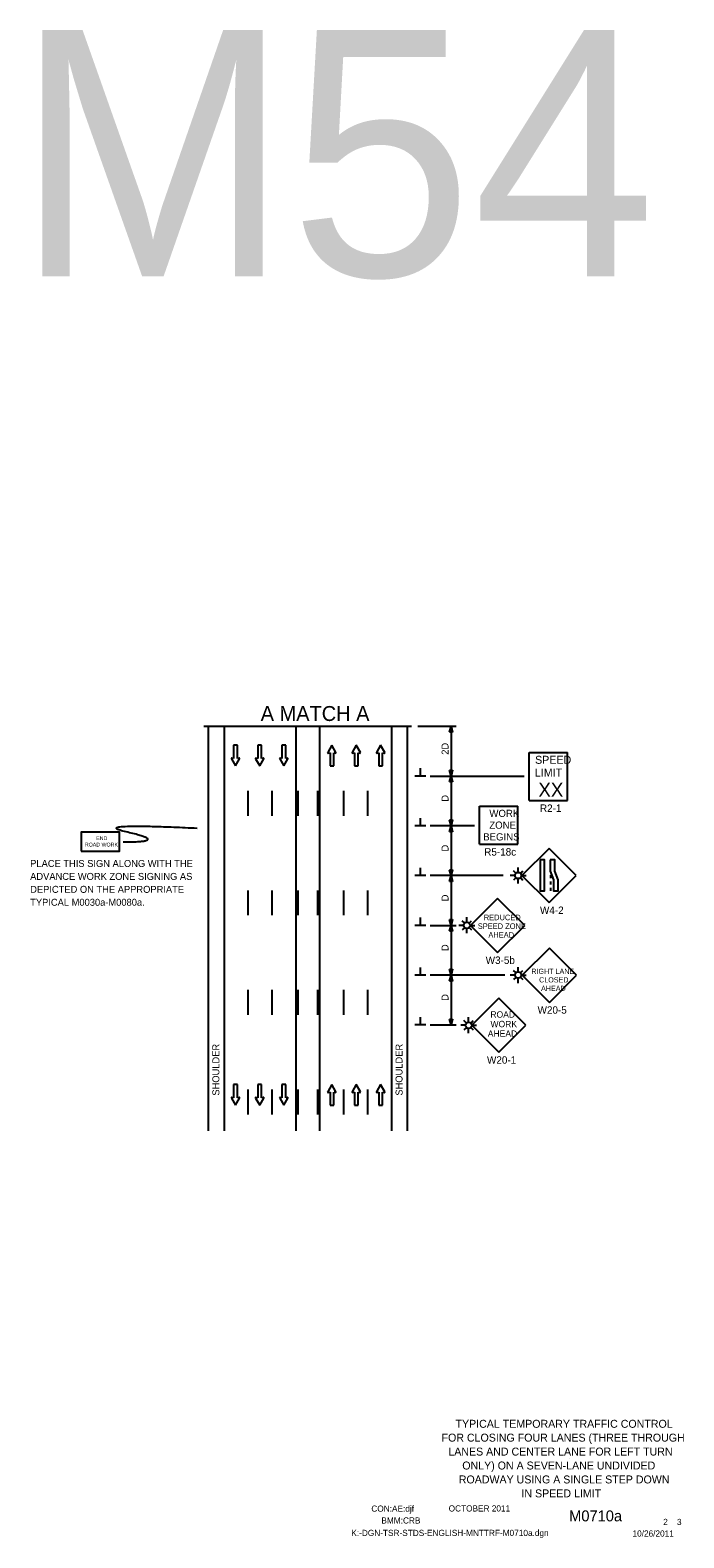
# Model space of a CAD drawing. Extents: x 16731 to 19504, y 5932 to 7446.
# Drawn here: x 17777 to 18433, y 5932 to 7446 of the extents above; entities that cross this region are included whole.
import ezdxf

# ---------------------------------------------------------------- set-up
doc = ezdxf.new("R2010")
doc.units = 0
for name, color, linetype in [('ALI_LEGAL_EX', 7, 'Continuous'), ('BORDER', 7, 'Continuous'), ('BORDER_SIGNAL_WO', 7, 'Continuous'), ('MT_SCRATCH_LEVEL_E', 7, 'Continuous'), ('PAVT_EDGE_EX', 7, 'Continuous'), ('TRAFFIC_SIGNS_PR', 7, 'Continuous'), ('TYPICAL_TEXT_DIMEN_PR', 7, 'Continuous')]:
    doc.layers.add(name, color=color, linetype=linetype)

msp = doc.modelspace()

# ---------------------------------------------------------------- linework, layer by layer
at = {"layer": 'ALI_LEGAL_EX'}
for points in [[(17995.8, 6682.2), (17995.8, 6657.2)], [(18019.8, 6682.2), (18019.8, 6657.2)], [(18045.8, 6682.2), (18045.8, 6657.2)], [(18065.8, 6682.2), (18065.8, 6657.2)], [(18091.8, 6682.2), (18091.8, 6657.2)], [(18115.8, 6682.2), (18115.8, 6657.2)], [(17995.8, 6582.2), (17995.8, 6557.2)], [(18019.8, 6582.2), (18019.8, 6557.2)], [(18045.8, 6582.2), (18045.8, 6557.2)], [(18065.8, 6582.2), (18065.8, 6557.2)], [(18091.8, 6582.2), (18091.8, 6557.2)], [(18115.8, 6582.2), (18115.8, 6557.2)], [(17995.8, 6482.2), (17995.8, 6457.2)], [(18019.8, 6482.2), (18019.8, 6457.2)], [(18045.8, 6482.2), (18045.8, 6457.2)], [(18065.8, 6482.2), (18065.8, 6457.2)], [(18091.8, 6482.2), (18091.8, 6457.2)], [(18115.8, 6482.2), (18115.8, 6457.2)], [(17995.8, 6382.2), (17995.8, 6357.2)], [(18019.8, 6382.2), (18019.8, 6357.2)], [(18045.8, 6382.2), (18045.8, 6357.2)], [(18065.8, 6382.2), (18065.8, 6357.2)], [(18091.8, 6382.2), (18091.8, 6357.2)], [(18115.8, 6382.2), (18115.8, 6357.2)]]:
    msp.add_lwpolyline(points, dxfattribs=at)
at = {"layer": 'BORDER'}
msp.add_line((18318.2, 6011.2), (18318.2, 6011.2), dxfattribs=at)
msp.add_line((18318.2, 6011.2), (18318.2, 6011.2), dxfattribs=at)
at = {"layer": 'MT_SCRATCH_LEVEL_E'}
for p, q in [((17985.2, 6727.9), (17981.4, 6727.9)), ((17981.4, 6727.9), (17981.4, 6714.7)), ((17985.2, 6727.9), (17981.4, 6727.9)), ((17981.4, 6727.9), (17981.4, 6714.7)), ((17985.2, 6714.7), (17985.2, 6727.9)), ((17985.2, 6714.7), (17985.2, 6727.9)), ((18009.4, 6727.9), (18005.7, 6727.9)), ((18005.7, 6727.9), (18005.7, 6714.7)), ((18009.4, 6727.9), (18005.7, 6727.9)), ((18005.7, 6727.9), (18005.7, 6714.7)), ((18009.4, 6714.7), (18009.4, 6727.9)), ((18009.4, 6714.7), (18009.4, 6727.9)), ((18033.7, 6727.9), (18030, 6727.9)), ((18030, 6727.9), (18030, 6714.7)), ((18033.7, 6727.9), (18030, 6727.9)), ((18030, 6727.9), (18030, 6714.7)), ((18033.7, 6714.7), (18033.7, 6727.9)), ((18033.7, 6714.7), (18033.7, 6727.9)), ((18080, 6727.9), (18075.9, 6720.7)), ((18080, 6727.9), (18075.9, 6720.7)), ((18084.2, 6720.7), (18080, 6727.9)), ((18084.2, 6720.7), (18080, 6727.9)), ((18104.5, 6727.9), (18100.4, 6720.7)), ((18104.5, 6727.9), (18100.4, 6720.7)), ((18108.7, 6720.7), (18104.5, 6727.9)), ((18108.7, 6720.7), (18104.5, 6727.9)), ((18129, 6727.9), (18124.9, 6720.7)), ((18129, 6727.9), (18124.9, 6720.7)), ((18133.2, 6720.7), (18129, 6727.9)), ((18133.2, 6720.7), (18129, 6727.9)), ((17979.2, 6714.3), (17983.3, 6707.1)), ((17979.2, 6714.3), (17983.3, 6707.1)), ((17981.4, 6714.7), (17979.7, 6715)), ((17981.4, 6714.7), (17979.7, 6715)), ((17983.3, 6707.1), (17987.4, 6714.3)), ((17983.3, 6707.1), (17987.4, 6714.3)), ((17987, 6715), (17985.2, 6714.7)), ((17987, 6715), (17985.2, 6714.7)), ((18003.4, 6714.3), (18007.6, 6707.1)), ((18003.4, 6714.3), (18007.6, 6707.1)), ((18005.7, 6714.7), (18003.9, 6715)), ((18005.7, 6714.7), (18003.9, 6715)), ((18007.6, 6707.1), (18011.7, 6714.3)), ((18007.6, 6707.1), (18011.7, 6714.3)), ((18011.2, 6715), (18009.4, 6714.7)), ((18011.2, 6715), (18009.4, 6714.7)), ((18027.7, 6714.3), (18031.8, 6707.1)), ((18027.7, 6714.3), (18031.8, 6707.1)), ((18030, 6714.7), (18028.2, 6715)), ((18030, 6714.7), (18028.2, 6715)), ((18031.8, 6707.1), (18036, 6714.3)), ((18031.8, 6707.1), (18036, 6714.3)), ((18035.5, 6715), (18033.7, 6714.7)), ((18035.5, 6715), (18033.7, 6714.7)), ((18076.4, 6720), (18078.2, 6720.3)), ((18076.4, 6720), (18078.2, 6720.3)), ((18078.2, 6720.3), (18078.2, 6707.1)), ((18078.2, 6720.3), (18078.2, 6707.1)), ((18081.9, 6707.1), (18081.9, 6720.3)), ((18081.9, 6720.3), (18083.7, 6720)), ((18081.9, 6707.1), (18081.9, 6720.3)), ((18081.9, 6720.3), (18083.7, 6720)), ((18100.9, 6720), (18102.7, 6720.3)), ((18100.9, 6720), (18102.7, 6720.3)), ((18102.7, 6720.3), (18102.7, 6707.1)), ((18102.7, 6720.3), (18102.7, 6707.1)), ((18106.4, 6707.1), (18106.4, 6720.3)), ((18106.4, 6720.3), (18108.2, 6720)), ((18106.4, 6707.1), (18106.4, 6720.3)), ((18106.4, 6720.3), (18108.2, 6720)), ((18125.4, 6720), (18127.2, 6720.3)), ((18125.4, 6720), (18127.2, 6720.3)), ((18127.2, 6720.3), (18127.2, 6707.1)), ((18127.2, 6720.3), (18127.2, 6707.1)), ((18130.9, 6707.1), (18130.9, 6720.3)), ((18130.9, 6720.3), (18132.7, 6720)), ((18130.9, 6707.1), (18130.9, 6720.3)), ((18130.9, 6720.3), (18132.7, 6720)), ((18078.2, 6707.1), (18081.9, 6707.1)), ((18078.2, 6707.1), (18081.9, 6707.1)), ((18102.7, 6707.1), (18106.4, 6707.1)), ((18102.7, 6707.1), (18106.4, 6707.1)), ((18127.2, 6707.1), (18130.9, 6707.1)), ((18127.2, 6707.1), (18130.9, 6707.1)), ((17985.2, 6387.1), (17981.4, 6387.1)), ((17981.4, 6387.1), (17981.4, 6373.9)), ((17985.2, 6387.1), (17981.4, 6387.1)), ((17981.4, 6387.1), (17981.4, 6373.9)), ((17985.2, 6373.9), (17985.2, 6387.1)), ((17985.2, 6373.9), (17985.2, 6387.1)), ((18009.4, 6387.1), (18005.7, 6387.1)), ((18005.7, 6387.1), (18005.7, 6373.9)), ((18009.4, 6387.1), (18005.7, 6387.1)), ((18005.7, 6387.1), (18005.7, 6373.9)), ((18009.4, 6373.9), (18009.4, 6387.1)), ((18009.4, 6373.9), (18009.4, 6387.1)), ((18033.7, 6387.1), (18030, 6387.1)), ((18030, 6387.1), (18030, 6373.9)), ((18033.7, 6387.1), (18030, 6387.1)), ((18030, 6387.1), (18030, 6373.9)), ((18033.7, 6373.9), (18033.7, 6387.1)), ((18033.7, 6373.9), (18033.7, 6387.1)), ((18080, 6387.1), (18075.9, 6379.9)), ((18080, 6387.1), (18075.9, 6379.9)), ((18076.4, 6379.2), (18078.2, 6379.5)), ((18076.4, 6379.2), (18078.2, 6379.5)), ((18078.2, 6379.5), (18078.2, 6366.3)), ((18078.2, 6379.5), (18078.2, 6366.3)), ((18084.2, 6379.9), (18080, 6387.1)), ((18084.2, 6379.9), (18080, 6387.1)), ((18081.9, 6366.3), (18081.9, 6379.5)), ((18081.9, 6379.5), (18083.7, 6379.2)), ((18081.9, 6366.3), (18081.9, 6379.5)), ((18081.9, 6379.5), (18083.7, 6379.2)), ((18104.5, 6387.1), (18100.4, 6379.9)), ((18104.5, 6387.1), (18100.4, 6379.9)), ((18100.9, 6379.2), (18102.7, 6379.5)), ((18100.9, 6379.2), (18102.7, 6379.5)), ((18102.7, 6379.5), (18102.7, 6366.3)), ((18102.7, 6379.5), (18102.7, 6366.3)), ((18108.7, 6379.9), (18104.5, 6387.1)), ((18108.7, 6379.9), (18104.5, 6387.1)), ((18106.4, 6366.3), (18106.4, 6379.5)), ((18106.4, 6379.5), (18108.2, 6379.2)), ((18106.4, 6366.3), (18106.4, 6379.5)), ((18106.4, 6379.5), (18108.2, 6379.2)), ((18129, 6387.1), (18124.9, 6379.9)), ((18129, 6387.1), (18124.9, 6379.9)), ((18125.4, 6379.2), (18127.2, 6379.5)), ((18125.4, 6379.2), (18127.2, 6379.5)), ((18127.2, 6379.5), (18127.2, 6366.3)), ((18127.2, 6379.5), (18127.2, 6366.3)), ((18133.2, 6379.9), (18129, 6387.1)), ((18133.2, 6379.9), (18129, 6387.1)), ((18130.9, 6366.3), (18130.9, 6379.5)), ((18130.9, 6379.5), (18132.7, 6379.2)), ((18130.9, 6366.3), (18130.9, 6379.5)), ((18130.9, 6379.5), (18132.7, 6379.2)), ((17979.2, 6373.5), (17983.3, 6366.3)), ((17979.2, 6373.5), (17983.3, 6366.3)), ((17981.4, 6373.9), (17979.7, 6374.2)), ((17981.4, 6373.9), (17979.7, 6374.2)), ((17983.3, 6366.3), (17987.4, 6373.5)), ((17983.3, 6366.3), (17987.4, 6373.5)), ((17987, 6374.2), (17985.2, 6373.9)), ((17987, 6374.2), (17985.2, 6373.9)), ((18003.4, 6373.5), (18007.6, 6366.3)), ((18003.4, 6373.5), (18007.6, 6366.3)), ((18005.7, 6373.9), (18003.9, 6374.2)), ((18005.7, 6373.9), (18003.9, 6374.2)), ((18007.6, 6366.3), (18011.7, 6373.5)), ((18007.6, 6366.3), (18011.7, 6373.5)), ((18011.2, 6374.2), (18009.4, 6373.9)), ((18011.2, 6374.2), (18009.4, 6373.9)), ((18027.7, 6373.5), (18031.8, 6366.3)), ((18027.7, 6373.5), (18031.8, 6366.3)), ((18030, 6373.9), (18028.2, 6374.2)), ((18030, 6373.9), (18028.2, 6374.2)), ((18031.8, 6366.3), (18036, 6373.5)), ((18031.8, 6366.3), (18036, 6373.5)), ((18035.5, 6374.2), (18033.7, 6373.9)), ((18035.5, 6374.2), (18033.7, 6373.9)), ((18078.2, 6366.3), (18081.9, 6366.3)), ((18078.2, 6366.3), (18081.9, 6366.3)), ((18102.7, 6366.3), (18106.4, 6366.3)), ((18102.7, 6366.3), (18106.4, 6366.3)), ((18127.2, 6366.3), (18130.9, 6366.3)), ((18127.2, 6366.3), (18130.9, 6366.3))]:
    msp.add_line(p, q, dxfattribs=at)
for centre, start, end in [((17979.6, 6714.5), 80.0362, 209.7731), ((17979.6, 6714.5), 80.0362, 209.7731), ((17987, 6714.5), 330.4248, 99.9638), ((17987, 6714.5), 330.4248, 99.9638), ((18003.8, 6714.5), 80.0362, 209.7731), ((18003.8, 6714.5), 80.0362, 209.7731), ((18011.3, 6714.5), 330.4248, 99.9638), ((18011.3, 6714.5), 330.4248, 99.9638), ((18028.1, 6714.5), 80.0362, 209.7731), ((18028.1, 6714.5), 80.0362, 209.7731), ((18035.5, 6714.5), 330.4248, 99.9638), ((18035.5, 6714.5), 330.4248, 99.9638), ((18076.3, 6720.5), 150.4248, 279.9638), ((18076.3, 6720.5), 150.4248, 279.9638), ((18083.7, 6720.5), 260.0362, 29.7731), ((18083.7, 6720.5), 260.0362, 29.7731), ((18100.8, 6720.5), 150.4248, 279.9638), ((18100.8, 6720.5), 150.4248, 279.9638), ((18108.2, 6720.5), 260.0362, 29.7731), ((18108.2, 6720.5), 260.0362, 29.7731), ((18125.3, 6720.5), 150.4248, 279.9638), ((18125.3, 6720.5), 150.4248, 279.9638), ((18132.7, 6720.5), 260.0362, 29.7731), ((18132.7, 6720.5), 260.0362, 29.7731), ((18076.3, 6379.7), 150.4248, 279.9638), ((18076.3, 6379.7), 150.4248, 279.9638), ((18083.7, 6379.7), 260.0362, 29.7731), ((18083.7, 6379.7), 260.0362, 29.7731), ((18100.8, 6379.7), 150.4248, 279.9638), ((18100.8, 6379.7), 150.4248, 279.9638), ((18108.2, 6379.7), 260.0362, 29.7731), ((18108.2, 6379.7), 260.0362, 29.7731), ((18125.3, 6379.7), 150.4248, 279.9638), ((18125.3, 6379.7), 150.4248, 279.9638), ((18132.7, 6379.7), 260.0362, 29.7731), ((18132.7, 6379.7), 260.0362, 29.7731), ((17979.6, 6373.7), 80.0362, 209.7731), ((17979.6, 6373.7), 80.0362, 209.7731), ((17987, 6373.7), 330.4248, 99.9638), ((17987, 6373.7), 330.4248, 99.9638), ((18003.8, 6373.7), 80.0362, 209.7731), ((18003.8, 6373.7), 80.0362, 209.7731), ((18011.3, 6373.7), 330.4248, 99.9638), ((18011.3, 6373.7), 330.4248, 99.9638), ((18028.1, 6373.7), 80.0362, 209.7731), ((18028.1, 6373.7), 80.0362, 209.7731), ((18035.5, 6373.7), 330.4248, 99.9638), ((18035.5, 6373.7), 330.4248, 99.9638)]:
    msp.add_arc(centre, 0.463, start, end, dxfattribs=at)
at = {"layer": 'PAVT_EDGE_EX'}
for p, q in [((17955.8, 6747), (17955.8, 6340.8)), ((17971.8, 6747), (17971.8, 6340.8)), ((18043.8, 6747), (18043.8, 6340.8)), ((18067.8, 6747), (18067.8, 6340.8)), ((18139.8, 6747), (18139.8, 6340.8)), ((18155.8, 6747), (18155.8, 6340.8))]:
    msp.add_line(p, q, dxfattribs=at)
at = {"layer": 'TRAFFIC_SIGNS_PR'}
for p, q in [((18278.3, 6720.5), (18316.7, 6720.5)), ((18278.3, 6672.5), (18278.3, 6720.5)), ((18316.7, 6672.5), (18316.7, 6720.5)), ((18228.2, 6628.5), (18228.2, 6666.9)), ((18228.2, 6666.9), (18266.6, 6666.9)), ((18266.6, 6628.5), (18266.6, 6666.9)), ((18278.3, 6672.5), (18316.7, 6672.5)), ((18228.2, 6628.5), (18266.6, 6628.5)), ((18298.1, 6624.2), (18270.9, 6597.1)), ((18325.2, 6597.1), (18298.1, 6624.2)), ((18267.1, 6600.6), (18267.1, 6605.1)), ((18264, 6597.1), (18259.1, 6597.1)), ((18264.6, 6599.6), (18262.5, 6601.7)), ((18264.6, 6594.6), (18262.5, 6592.4)), ((18267.1, 6589.1), (18267.1, 6593.5)), ((18269.7, 6599.6), (18271.8, 6601.7)), ((18269.7, 6594.6), (18271.8, 6592.4)), ((18270.3, 6597.1), (18275.2, 6597.1)), ((18270.9, 6597.1), (18298.1, 6569.9)), ((18298.1, 6569.9), (18325.2, 6597.1)), ((18299.7, 6597.6), (18299.7, 6594.4)), ((18299.7, 6591.2), (18299.7, 6588)), ((18246.5, 6574.1), (18219.4, 6546.9)), ((18273.7, 6546.9), (18246.5, 6574.1)), ((18299.7, 6584.8), (18299.7, 6581.6)), ((18212.5, 6547), (18207.6, 6547)), ((18213.1, 6549.6), (18211, 6551.7)), ((18213.1, 6544.5), (18211, 6542.4)), ((18215.6, 6550.6), (18215.6, 6555.1)), ((18215.6, 6539.1), (18215.6, 6543.5)), ((18218.1, 6549.6), (18220.2, 6551.7)), ((18218.1, 6544.5), (18220.2, 6542.4)), ((18218.8, 6547), (18223.7, 6547)), ((18219.4, 6546.9), (18246.5, 6519.8)), ((18246.5, 6519.8), (18273.7, 6546.9)), ((18298.4, 6524), (18271.2, 6496.9)), ((18325.5, 6496.9), (18298.4, 6524)), ((18264, 6497.1), (18259.1, 6497.1)), ((18264.6, 6499.6), (18262.5, 6501.7)), ((18267.1, 6500.6), (18267.1, 6505.1)), ((18269.7, 6499.6), (18271.8, 6501.7)), ((18270.3, 6497.1), (18275.2, 6497.1)), ((18271.2, 6496.9), (18298.4, 6469.7)), ((18298.4, 6469.7), (18325.5, 6496.9)), ((18264.6, 6494.6), (18262.5, 6492.5)), ((18267.1, 6489.1), (18267.1, 6493.5)), ((18269.7, 6494.6), (18271.8, 6492.5)), ((18247.7, 6473.9), (18220.5, 6446.7)), ((18274.9, 6446.7), (18247.7, 6473.9)), ((18214.8, 6449.2), (18212.7, 6451.4)), ((18217.3, 6450.3), (18217.3, 6454.8)), ((18219.9, 6449.2), (18222, 6451.4)), ((18214.2, 6446.7), (18209.4, 6446.7)), ((18214.8, 6444.2), (18212.7, 6442.1)), ((18217.3, 6438.8), (18217.3, 6443.2)), ((18219.9, 6444.2), (18222, 6442.1)), ((18220.5, 6446.7), (18225.4, 6446.7)), ((18220.5, 6446.7), (18247.7, 6419.5)), ((18247.7, 6419.5), (18274.9, 6446.7))]:
    msp.add_line(p, q, dxfattribs=at)
for points in [[(17828.5, 6621.4), (17866.9, 6621.4), (17866.9, 6640.6), (17828.5, 6640.6)], [(18289.2, 6612.8), (18289.2, 6581.6), (18293.6, 6581.6), (18293.6, 6612.8)], [(18299.3, 6612.8), (18299.3, 6601.6), (18302.6, 6592.7), (18302.6, 6581.6), (18307.1, 6581.6), (18307.1, 6592.7), (18303.8, 6601.6), (18303.8, 6612.8)]]:
    msp.add_lwpolyline(points, close=True, dxfattribs=at)
for centre in [(18267.1, 6597.1), (18215.6, 6547), (18267.1, 6497.1), (18217.4, 6446.7)]:
    msp.add_circle(centre, 3.15, dxfattribs=at)
msp.add_open_spline([(17870.4, 6630.8), (17917.7, 6630.8), (17832.7, 6650.2), (17945, 6644.7)], degree=2, dxfattribs=at)
at = {"layer": 'TYPICAL_TEXT_DIMEN_PR'}
for p, q in [((17951.5, 6747), (18160.1, 6747)), ((18043.8, 6747), (18067.8, 6747)), ((18166.5, 6747), (18204.8, 6747)), ((18198.2, 6741.1), (18199.8, 6747)), ((18199.8, 6741.1), (18198.2, 6741.1)), ((18199.8, 6747), (18201.3, 6741.1)), ((18199.8, 6747), (18199.8, 6697)), ((18201.3, 6741.1), (18199.8, 6741.1)), ((18174.5, 6697), (18163.3, 6697)), ((18168.9, 6697), (18168.9, 6704.8)), ((18178.8, 6697), (18273.2, 6697)), ((18199.8, 6697), (18198.2, 6702.9)), ((18198.2, 6702.9), (18199.8, 6702.9)), ((18198.2, 6691.1), (18199.8, 6697)), ((18199.8, 6702.9), (18201.3, 6702.9)), ((18201.3, 6702.9), (18199.8, 6697)), ((18199.8, 6697), (18201.3, 6691.1)), ((18199.8, 6697), (18199.8, 6647)), ((18199.8, 6691.1), (18198.2, 6691.1)), ((18201.3, 6691.1), (18199.8, 6691.1)), ((18168.9, 6647), (18168.9, 6654.8)), ((18199.8, 6647), (18198.2, 6652.9)), ((18198.2, 6652.9), (18199.8, 6652.9)), ((18199.8, 6652.9), (18201.3, 6652.9)), ((18201.3, 6652.9), (18199.8, 6647)), ((18174.5, 6647), (18163.3, 6647)), ((18223.2, 6647), (18178.8, 6647)), ((18198.2, 6641.1), (18199.8, 6647)), ((18199.8, 6641.1), (18198.2, 6641.1)), ((18199.8, 6647), (18201.3, 6641.1)), ((18199.8, 6647), (18199.8, 6597)), ((18201.3, 6641.1), (18199.8, 6641.1)), ((18168.9, 6597), (18168.9, 6604.8)), ((18199.8, 6597), (18198.2, 6602.9)), ((18198.2, 6602.9), (18199.8, 6602.9)), ((18199.8, 6602.9), (18201.3, 6602.9)), ((18201.3, 6602.9), (18199.8, 6597)), ((18174.5, 6597), (18163.3, 6597)), ((18252, 6597), (18178.8, 6597)), ((18198.2, 6591.1), (18199.8, 6597)), ((18199.8, 6591.1), (18198.2, 6591.1)), ((18199.8, 6597), (18201.3, 6591.1)), ((18199.8, 6597), (18199.8, 6547)), ((18201.3, 6591.1), (18199.8, 6591.1)), ((18174.5, 6547), (18163.3, 6547)), ((18168.9, 6547), (18168.9, 6554.8)), ((18178.8, 6547), (18204.8, 6547)), ((18199.8, 6547), (18198.2, 6552.9)), ((18198.2, 6552.9), (18199.8, 6552.9)), ((18198.2, 6541.1), (18199.8, 6547)), ((18199.8, 6552.9), (18201.3, 6552.9)), ((18201.3, 6552.9), (18199.8, 6547)), ((18199.8, 6547), (18201.3, 6541.1)), ((18199.8, 6547), (18199.8, 6497)), ((18199.8, 6541.1), (18198.2, 6541.1)), ((18201.3, 6541.1), (18199.8, 6541.1)), ((18174.5, 6497), (18163.3, 6497)), ((18168.9, 6497), (18168.9, 6504.8)), ((18253.7, 6497), (18178.8, 6497)), ((18199.8, 6497), (18198.2, 6502.9)), ((18198.2, 6502.9), (18199.8, 6502.9)), ((18198.2, 6491.1), (18199.8, 6497)), ((18199.8, 6502.9), (18201.3, 6502.9)), ((18201.3, 6502.9), (18199.8, 6497)), ((18199.8, 6497), (18201.3, 6491.1)), ((18199.8, 6497), (18199.8, 6447)), ((18199.8, 6491.1), (18198.2, 6491.1)), ((18201.3, 6491.1), (18199.8, 6491.1)), ((18168.9, 6447), (18168.9, 6454.8)), ((18199.8, 6447), (18198.2, 6452.9)), ((18198.2, 6452.9), (18199.8, 6452.9)), ((18199.8, 6452.9), (18201.3, 6452.9)), ((18201.3, 6452.9), (18199.8, 6447)), ((18174.5, 6447), (18163.3, 6447)), ((18178.8, 6447), (18204.8, 6447))]:
    msp.add_line(p, q, dxfattribs=at)

# ---------------------------------------------------------------- texts
at = {"layer": 'BORDER_SIGNAL_WO'}
for s, height, p in [('TYPICAL TEMPORARY TRAFFIC CONTROL', 7.974, (18204.2, 6042.4)), ('FOR CLOSING FOUR LANES (THREE THROUGH', 7.974, (18190.2, 6028.5)), ('LANES AND CENTER LANE FOR LEFT TURN', 7.974, (18197, 6014.5)), ('ONLY) ON A SEVEN-LANE UNDIVIDED', 7.974, (18211, 6000.5)), ('ROADWAY USING A SINGLE STEP DOWN', 7.974, (18207.5, 5986.5)), ('IN SPEED LIMIT', 7.974, (18270.4, 5972.5)), ('CON:AE:djf', 6.2, (18119.7, 5958.1)), ('BMM:CRB   ', 6.2, (18129.8, 5946.2)), ('    OCTOBER 2011    ', 6.2, (18188.1, 5958.3)), ('    M0710a   ', 11, (18301.9, 5948.4)), ('K:-DGN-TSR-STDS-ENGLISH-MNTTRF-M0710a.dgn        ', 6.2, (18099.6, 5933.7)), ('10/26/2011    ', 6.2, (18381.9, 5933.1)), (' 2    3 ', 6.2, (18410.4, 5944.7))]:
    msp.add_text(s, height=height, dxfattribs=at).set_placement(p)
at = {"layer": 'TRAFFIC_SIGNS_PR'}
for s, height, p in [('SPEED', 8, (18284.1, 6709.3)), ('LIMIT', 8, (18283.9, 6696.5)), ('XX', 14.03, (18287.4, 6676.2)), ('WORK', 7.22, (18238.2, 6655.9)), ('R2-1', 7.44, (18289, 6661)), ('ZONE', 7.22, (18238.1, 6644.1)), ('END', 3.83, (17843.5, 6632.6)), ('BEGINS', 7.22, (18232, 6632.3)), ('ROAD WORK', 3.83, (17832.1, 6626.2)), ('R5-18c', 7.44, (18233, 6617.1)), ('PLACE THIS SIGN ALONG WITH THE', 7, (17777.2, 6605.7)), ('ADVANCE WORK ZONE SIGNING AS', 7, (17777.2, 6592.7)), ('TYPICAL M0030a-M0080a.', 7, (17777.2, 6566.7)), ('DEPICTED ON THE APPROPRIATE', 7, (17777.2, 6579.7)), ('REDUCED', 5.6, (18232.6, 6552.2)), ('W4-2', 7.44, (18289, 6558.5)), ('SPEED ZONE', 5.6, (18226.6, 6543.4)), ('AHEAD', 5.6, (18237.2, 6534.6)), ('W3-5b', 7.44, (18234.5, 6508.3)), ('RIGHT LANE', 5.2, (18280.3, 6498.3)), ('CLOSED', 5.2, (18288.1, 6489.7)), ('AHEAD', 5.2, (18290.1, 6481.1)), ('WORK', 6.41, (18239.3, 6444.7)), ('ROAD', 6.41, (18239.2, 6454.3)), ('W20-5', 7.44, (18286.6, 6458.3)), ('AHEAD', 6.41, (18236.6, 6435.1)), ('W20-1', 7.45, (18235.8, 6408.1))]:
    msp.add_text(s, height=height, dxfattribs=at).set_placement(p)
at = {"layer": 'TYPICAL_TEXT_DIMEN_PR'}
for s, height, p in [('M54', 247.21, (17762.2, 7199)), ('A MATCH A', 15, (18008.6, 6752.3))]:
    msp.add_text(s, height=height, dxfattribs=at).set_placement(p)
for s, p in [('2D', (18197.2, 6718.4)), ('D', (18197.2, 6671.2)), ('D', (18197.2, 6621.2)), ('D', (18197.2, 6571.2)), ('D', (18197.2, 6521.2)), ('D', (18197.2, 6471.2)), ('SHOULDER', (17967.1, 6376)), ('SHOULDER', (18151, 6376))]:
    msp.add_text(s, height=7, rotation=90, dxfattribs=at).set_placement(p)

doc.saveas('drawing.dxf')
